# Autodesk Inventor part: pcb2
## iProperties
Shininess: 64.0
Length Units: 11269
Angle Units: 11279
Time Units: 11290
Mass Units: 11283
Length Display Precision: 3
Angle Display Precision: 2
Compacted: True
Part Number: pcb2
Document SubType Name: Modeling
Created: 2003-06
Designer: John Blackburn
Density: 0.0
Volumn: 0.0
Area: 0.0
PropertySet Name: Model Information
Control State: 0
Master: False
Checked Out: False
Author: John Blackburn
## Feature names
1. Extrusion1
2. Hole1
